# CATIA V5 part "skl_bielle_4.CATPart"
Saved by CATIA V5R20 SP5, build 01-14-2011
Part number: skl_bielle_4
Publications: "Point.1", "Point.2", "Plan_ref", "Axe_pivot_bielle_4_bielle_2_3", "Axe_pivot_bielle_4_coulisseau"
Bounding box of the stored display mesh (mm): x -10 to 10, y 0 to 90, z 100 to 100
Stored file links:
  U:\2A\IAO\ThinkMotion\skl_bielle_4.CATPart
  U:\2A\IAO\ThinkMotion\skl.CATProduct
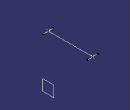
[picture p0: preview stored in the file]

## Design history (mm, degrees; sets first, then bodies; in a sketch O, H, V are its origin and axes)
Set1
  Point1: linked copy from another document
  Point2: linked copy from another document
  Plane1 "Plan_ref": linked copy from another document
Set2
  Line1: type PtPt, FirstPoint Point1, SecondPoint Point2
  Line2 "Axe_pivot_bielle_4_bielle_2_3": type Normal, RefPoint Point1, RefSkin Plane1, Start -10, End 10
  Line3 "Axe_pivot_bielle_4_coulisseau": type Normal, RefPoint Point2, RefSkin Plane1, Start -10, End 10
Body1 (main body)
